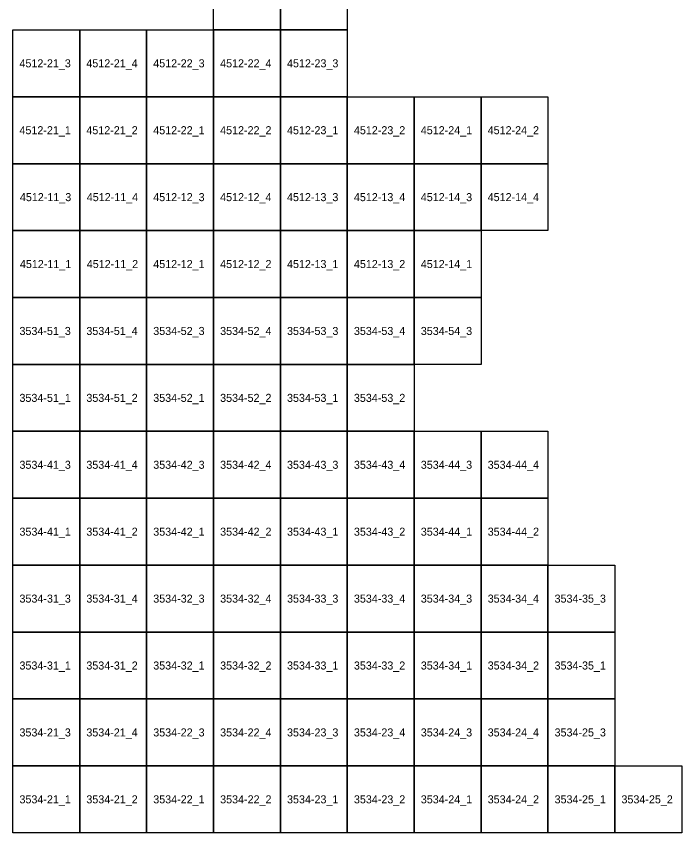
# Model space of a CAD drawing. Extents: x 312500 to 765000, y 172500 to 440000.
# Drawn here: x 725129 to 750000, y 280078 to 310507 of the extents above; entities that cross this region are included whole.
import ezdxf

# ---------------------------------------------------------------- set-up
doc = ezdxf.new("R2010")
doc.units = 0
doc.layers.add('Topo5_ramis_TKS2025', color=7, linetype='Continuous')
doc.layers.add('Topo5_ramis_TKS2025_Nr', color=7, linetype='Continuous')

msp = doc.modelspace()

# ---------------------------------------------------------------- linework, layer by layer
at = {"layer": 'Topo5_ramis_TKS2025'}
for points in [[(732500, 310000), (732500, 312500), (735000, 312500), (735000, 310000), (732500, 310000)], [(735000, 310000), (735000, 312500), (737500, 312500), (737500, 310000), (735000, 310000)], [(725000, 307500), (725000, 310000), (727500, 310000), (727500, 307500), (725000, 307500)], [(727500, 307500), (727500, 310000), (730000, 310000), (730000, 307500), (727500, 307500)], [(730000, 307500), (730000, 310000), (732500, 310000), (732500, 307500), (730000, 307500)], [(732500, 307500), (732500, 310000), (735000, 310000), (735000, 307500), (732500, 307500)], [(735000, 307500), (735000, 310000), (737500, 310000), (737500, 307500), (735000, 307500)], [(725000, 305000), (725000, 307500), (727500, 307500), (727500, 305000), (725000, 305000)], [(727500, 305000), (727500, 307500), (730000, 307500), (730000, 305000), (727500, 305000)], [(730000, 305000), (730000, 307500), (732500, 307500), (732500, 305000), (730000, 305000)], [(732500, 305000), (732500, 307500), (735000, 307500), (735000, 305000), (732500, 305000)], [(735000, 305000), (735000, 307500), (737500, 307500), (737500, 305000), (735000, 305000)], [(737500, 305000), (737500, 307500), (740000, 307500), (740000, 305000), (737500, 305000)], [(740000, 305000), (740000, 307500), (742500, 307500), (742500, 305000), (740000, 305000)], [(742500, 305000), (742500, 307500), (745000, 307500), (745000, 305000), (742500, 305000)], [(725000, 302500), (725000, 305000), (727500, 305000), (727500, 302500), (725000, 302500)], [(727500, 302500), (727500, 305000), (730000, 305000), (730000, 302500), (727500, 302500)], [(730000, 302500), (730000, 305000), (732500, 305000), (732500, 302500), (730000, 302500)], [(732500, 302500), (732500, 305000), (735000, 305000), (735000, 302500), (732500, 302500)], [(735000, 302500), (735000, 305000), (737500, 305000), (737500, 302500), (735000, 302500)], [(737500, 302500), (737500, 305000), (740000, 305000), (740000, 302500), (737500, 302500)], [(740000, 302500), (740000, 305000), (742500, 305000), (742500, 302500), (740000, 302500)], [(742500, 302500), (742500, 305000), (745000, 305000), (745000, 302500), (742500, 302500)], [(725000, 300000), (725000, 302500), (727500, 302500), (727500, 300000), (725000, 300000)], [(727500, 300000), (727500, 302500), (730000, 302500), (730000, 300000), (727500, 300000)], [(730000, 300000), (730000, 302500), (732500, 302500), (732500, 300000), (730000, 300000)], [(732500, 300000), (732500, 302500), (735000, 302500), (735000, 300000), (732500, 300000)], [(735000, 300000), (735000, 302500), (737500, 302500), (737500, 300000), (735000, 300000)], [(737500, 300000), (737500, 302500), (740000, 302500), (740000, 300000), (737500, 300000)], [(740000, 300000), (740000, 302500), (742500, 302500), (742500, 300000), (740000, 300000)], [(725000, 297500), (725000, 300000), (727500, 300000), (727500, 297500), (725000, 297500)], [(727500, 297500), (727500, 300000), (730000, 300000), (730000, 297500), (727500, 297500)], [(730000, 297500), (730000, 300000), (732500, 300000), (732500, 297500), (730000, 297500)], [(732500, 297500), (732500, 300000), (735000, 300000), (735000, 297500), (732500, 297500)], [(735000, 297500), (735000, 300000), (737500, 300000), (737500, 297500), (735000, 297500)], [(737500, 297500), (737500, 300000), (740000, 300000), (740000, 297500), (737500, 297500)], [(740000, 297500), (740000, 300000), (742500, 300000), (742500, 297500), (740000, 297500)], [(725000, 295000), (725000, 297500), (727500, 297500), (727500, 295000), (725000, 295000)], [(727500, 295000), (727500, 297500), (730000, 297500), (730000, 295000), (727500, 295000)], [(730000, 295000), (730000, 297500), (732500, 297500), (732500, 295000), (730000, 295000)], [(732500, 295000), (732500, 297500), (735000, 297500), (735000, 295000), (732500, 295000)], [(735000, 295000), (735000, 297500), (737500, 297500), (737500, 295000), (735000, 295000)], [(737500, 295000), (737500, 297500), (740000, 297500), (740000, 295000), (737500, 295000)], [(725000, 292500), (725000, 295000), (727500, 295000), (727500, 292500), (725000, 292500)], [(727500, 292500), (727500, 295000), (730000, 295000), (730000, 292500), (727500, 292500)], [(730000, 292500), (730000, 295000), (732500, 295000), (732500, 292500), (730000, 292500)], [(732500, 292500), (732500, 295000), (735000, 295000), (735000, 292500), (732500, 292500)], [(735000, 292500), (735000, 295000), (737500, 295000), (737500, 292500), (735000, 292500)], [(737500, 292500), (737500, 295000), (740000, 295000), (740000, 292500), (737500, 292500)], [(740000, 292500), (740000, 295000), (742500, 295000), (742500, 292500), (740000, 292500)], [(742500, 292500), (742500, 295000), (745000, 295000), (745000, 292500), (742500, 292500)], [(725000, 290000), (725000, 292500), (727500, 292500), (727500, 290000), (725000, 290000)], [(727500, 290000), (727500, 292500), (730000, 292500), (730000, 290000), (727500, 290000)], [(730000, 290000), (730000, 292500), (732500, 292500), (732500, 290000), (730000, 290000)], [(732500, 290000), (732500, 292500), (735000, 292500), (735000, 290000), (732500, 290000)], [(735000, 290000), (735000, 292500), (737500, 292500), (737500, 290000), (735000, 290000)], [(737500, 290000), (737500, 292500), (740000, 292500), (740000, 290000), (737500, 290000)], [(740000, 290000), (740000, 292500), (742500, 292500), (742500, 290000), (740000, 290000)], [(742500, 290000), (742500, 292500), (745000, 292500), (745000, 290000), (742500, 290000)], [(725000, 287500), (725000, 290000), (727500, 290000), (727500, 287500), (725000, 287500)], [(727500, 287500), (727500, 290000), (730000, 290000), (730000, 287500), (727500, 287500)], [(730000, 287500), (730000, 290000), (732500, 290000), (732500, 287500), (730000, 287500)], [(732500, 287500), (732500, 290000), (735000, 290000), (735000, 287500), (732500, 287500)], [(735000, 287500), (735000, 290000), (737500, 290000), (737500, 287500), (735000, 287500)], [(737500, 287500), (737500, 290000), (740000, 290000), (740000, 287500), (737500, 287500)], [(740000, 287500), (740000, 290000), (742500, 290000), (742500, 287500), (740000, 287500)], [(742500, 287500), (742500, 290000), (745000, 290000), (745000, 287500), (742500, 287500)], [(745000, 287500), (745000, 290000), (747500, 290000), (747500, 287500), (745000, 287500)], [(725000, 285000), (725000, 287500), (727500, 287500), (727500, 285000), (725000, 285000)], [(727500, 285000), (727500, 287500), (730000, 287500), (730000, 285000), (727500, 285000)], [(730000, 285000), (730000, 287500), (732500, 287500), (732500, 285000), (730000, 285000)], [(732500, 285000), (732500, 287500), (735000, 287500), (735000, 285000), (732500, 285000)], [(735000, 285000), (735000, 287500), (737500, 287500), (737500, 285000), (735000, 285000)], [(737500, 285000), (737500, 287500), (740000, 287500), (740000, 285000), (737500, 285000)], [(740000, 285000), (740000, 287500), (742500, 287500), (742500, 285000), (740000, 285000)], [(742500, 285000), (742500, 287500), (745000, 287500), (745000, 285000), (742500, 285000)], [(745000, 285000), (745000, 287500), (747500, 287500), (747500, 285000), (745000, 285000)], [(725000, 282500), (725000, 285000), (727500, 285000), (727500, 282500), (725000, 282500)], [(727500, 282500), (727500, 285000), (730000, 285000), (730000, 282500), (727500, 282500)], [(730000, 282500), (730000, 285000), (732500, 285000), (732500, 282500), (730000, 282500)], [(732500, 282500), (732500, 285000), (735000, 285000), (735000, 282500), (732500, 282500)], [(735000, 282500), (735000, 285000), (737500, 285000), (737500, 282500), (735000, 282500)], [(737500, 282500), (737500, 285000), (740000, 285000), (740000, 282500), (737500, 282500)], [(740000, 282500), (740000, 285000), (742500, 285000), (742500, 282500), (740000, 282500)], [(742500, 282500), (742500, 285000), (745000, 285000), (745000, 282500), (742500, 282500)], [(745000, 282500), (745000, 285000), (747500, 285000), (747500, 282500), (745000, 282500)], [(725000, 280000), (725000, 282500), (727500, 282500), (727500, 280000), (725000, 280000)], [(727500, 280000), (727500, 282500), (730000, 282500), (730000, 280000), (727500, 280000)], [(730000, 280000), (730000, 282500), (732500, 282500), (732500, 280000), (730000, 280000)], [(732500, 280000), (732500, 282500), (735000, 282500), (735000, 280000), (732500, 280000)], [(735000, 280000), (735000, 282500), (737500, 282500), (737500, 280000), (735000, 280000)], [(737500, 280000), (737500, 282500), (740000, 282500), (740000, 280000), (737500, 280000)], [(740000, 280000), (740000, 282500), (742500, 282500), (742500, 280000), (740000, 280000)], [(742500, 280000), (742500, 282500), (745000, 282500), (745000, 280000), (742500, 280000)], [(745000, 280000), (745000, 282500), (747500, 282500), (747500, 280000), (745000, 280000)], [(747500, 280000), (747500, 282500), (750000, 282500), (750000, 280000), (747500, 280000)]]:
    msp.add_lwpolyline(points, dxfattribs=at)

# ---------------------------------------------------------------- texts
at = {"layer": 'Topo5_ramis_TKS2025_Nr'}
for s, p in [('4512-21_3', (725248, 308600)), ('4512-21_4', (727748, 308600)), ('4512-22_3', (730248, 308600)), ('4512-22_4', (732748, 308600)), ('4512-23_3', (735248, 308600)), ('4512-21_1', (725248, 306100)), ('4512-21_2', (727748, 306100)), ('4512-22_1', (730248, 306100)), ('4512-22_2', (732748, 306100)), ('4512-23_1', (735248, 306100)), ('4512-23_2', (737748, 306100)), ('4512-24_1', (740248, 306100)), ('4512-24_2', (742748, 306100)), ('4512-11_3', (725264, 303600)), ('4512-11_4', (727764, 303600)), ('4512-12_3', (730248, 303600)), ('4512-12_4', (732748, 303600)), ('4512-13_3', (735248, 303600)), ('4512-13_4', (737748, 303600)), ('4512-14_3', (740248, 303600)), ('4512-14_4', (742748, 303600)), ('4512-11_1', (725264, 301100)), ('4512-11_2', (727764, 301100)), ('4512-12_1', (730248, 301100)), ('4512-12_2', (732748, 301100)), ('4512-13_1', (735248, 301100)), ('4512-13_2', (737748, 301100)), ('4512-14_1', (740248, 301100)), ('3534-51_3', (725248, 298600)), ('3534-51_4', (727748, 298600)), ('3534-52_3', (730248, 298600)), ('3534-52_4', (732748, 298600)), ('3534-53_3', (735248, 298600)), ('3534-53_4', (737748, 298600)), ('3534-54_3', (740248, 298600)), ('3534-51_1', (725248, 296100)), ('3534-51_2', (727748, 296100)), ('3534-52_1', (730248, 296100)), ('3534-52_2', (732748, 296100)), ('3534-53_1', (735248, 296100)), ('3534-53_2', (737748, 296100)), ('3534-41_3', (725248, 293600)), ('3534-41_4', (727748, 293600)), ('3534-42_3', (730248, 293600)), ('3534-42_4', (732748, 293600)), ('3534-43_3', (735248, 293600)), ('3534-43_4', (737748, 293600)), ('3534-44_3', (740248, 293600)), ('3534-44_4', (742748, 293600)), ('3534-41_1', (725248, 291100)), ('3534-41_2', (727748, 291100)), ('3534-42_1', (730248, 291100)), ('3534-42_2', (732748, 291100)), ('3534-43_1', (735248, 291100)), ('3534-43_2', (737748, 291100)), ('3534-44_1', (740248, 291100)), ('3534-44_2', (742748, 291100)), ('3534-31_3', (725248, 288600)), ('3534-31_4', (727748, 288600)), ('3534-32_3', (730248, 288600)), ('3534-32_4', (732748, 288600)), ('3534-33_3', (735248, 288600)), ('3534-33_4', (737748, 288600)), ('3534-34_3', (740248, 288600)), ('3534-34_4', (742748, 288600)), ('3534-35_3', (745248, 288600)), ('3534-31_1', (725248, 286100)), ('3534-31_2', (727748, 286100)), ('3534-32_1', (730248, 286100)), ('3534-32_2', (732748, 286100)), ('3534-33_1', (735248, 286100)), ('3534-33_2', (737748, 286100)), ('3534-34_1', (740248, 286100)), ('3534-34_2', (742748, 286100)), ('3534-35_1', (745248, 286100)), ('3534-21_3', (725248, 283600)), ('3534-21_4', (727748, 283600)), ('3534-22_3', (730248, 283600)), ('3534-22_4', (732748, 283600)), ('3534-23_3', (735248, 283600)), ('3534-23_4', (737748, 283600)), ('3534-24_3', (740248, 283600)), ('3534-24_4', (742748, 283600)), ('3534-25_3', (745248, 283600)), ('3534-21_1', (725248, 281100)), ('3534-21_2', (727748, 281100)), ('3534-22_1', (730248, 281100)), ('3534-22_2', (732748, 281100)), ('3534-23_1', (735248, 281100)), ('3534-23_2', (737748, 281100)), ('3534-24_1', (740248, 281100)), ('3534-24_2', (742748, 281100)), ('3534-25_1', (745248, 281100)), ('3534-25_2', (747748, 281100))]:
    msp.add_text(s, height=300, dxfattribs=at).set_placement(p)

doc.saveas('drawing.dxf')
